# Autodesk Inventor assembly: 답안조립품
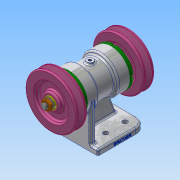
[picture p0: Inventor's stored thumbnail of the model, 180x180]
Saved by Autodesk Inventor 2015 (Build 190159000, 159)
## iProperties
Created: 2020-06
Part Number: 답안조립품
Document SubType Name: Assembly
Designer: user
Author: user
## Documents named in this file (12)
- C:\Users\user\Desktop\700606V1039\답안조립품.iam
- C:\Users\user\Desktop\700606V1039\본체.ipt
- C:\Users\user\Desktop\700606V1039\축.ipt
- C:\Users\user\Desktop\700606V1039\베어링 6204.ipt
- C:\Users\user\Desktop\700606V1039\오일 실 20 32 5.ipt
- C:\Users\user\Desktop\700606V1039\커버.ipt
- C:\Users\user\Desktop\700606V1039\키 5x5x12.ipt
- C:\Users\user\Desktop\700606V1039\V-벨트풀리.ipt
- C:\Users\user\Desktop\700606V1039\너트 M10.ipt
- C:\Users\user\Desktop\700606V1039\스프링 와셔 10.ipt
- C:\Users\user\Desktop\700606V1039\평면 와셔 10x21.ipt
- C:\Users\user\Desktop\700606V1039\볼트 M4.ipt
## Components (2 placed, 1 different names)
1. V-벨트풀리:1
2. V-벨트풀리:2
## Named parameters: d3_d2 = 0
